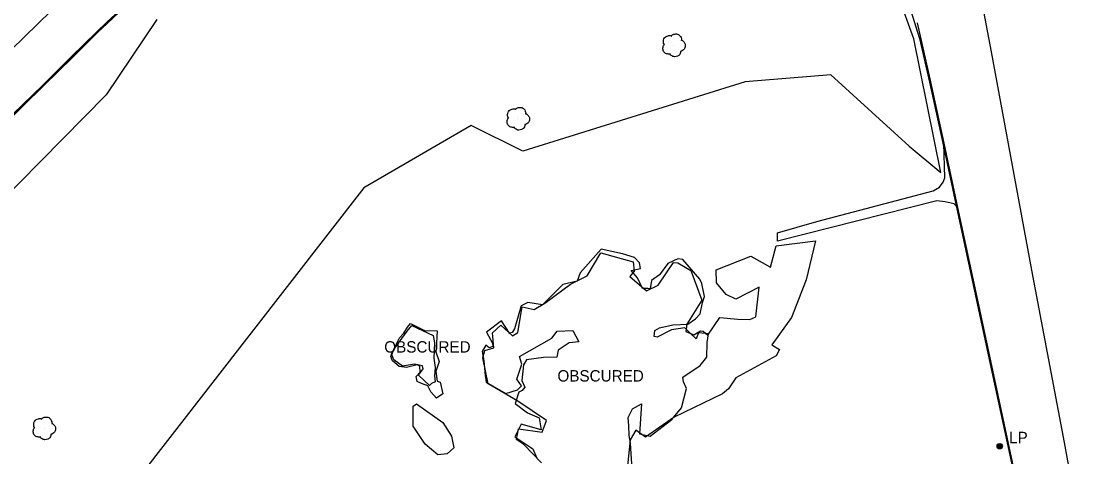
# Model space of a CAD drawing. Extents: x 368532 to 392481, y 10654822 to 10676899.
# Drawn here: x 374954.4 to 375423.4, y 10671119.3 to 10671309.9 of the extents above; entities that cross this region are included whole.
import ezdxf

# ---------------------------------------------------------------- set-up
doc = ezdxf.new("R2010")
doc.units = 0
for name, color, linetype in [('p_drainage conc drain', 7, 'Continuous'), ('p_dtm obscured area', 7, 'Continuous'), ('p_road - paved curb', 7, 'Continuous'), ('p_road guard rails', 7, 'Continuous'), ('p_road paint stripe', 7, 'Continuous'), ('p_structure constr area', 7, 'Continuous'), ('p_utility general pole', 7, 'Continuous'), ('p_veg tree', 7, 'Continuous'), ('p_veg woods', 7, 'Continuous')]:
    doc.layers.add(name, color=color, linetype=linetype)

msp = doc.modelspace()

# ---------------------------------------------------------------- linework, layer by layer
at = {"layer": 'p_drainage conc drain'}
for p, q in [((375359.42, 10671241.33), (375359, 10671256.53)), ((375357.15, 10671237.35), (375358.81, 10671239.52)), ((375358.81, 10671239.52), (375359.42, 10671241.33)), ((375303.34, 10671222.27), (375354.37, 10671235.67)), ((375354.37, 10671235.67), (375357.15, 10671237.35)), ((375356.05, 10671231.36), (375286.15, 10671213.72)), ((375359.64, 10671230.95), (375356.05, 10671231.36)), ((375363.54, 10671230.07), (375359.64, 10671230.95)), ((375365.09, 10671228.36), (375363.54, 10671230.07)), ((375286.11, 10671217.37), (375303.34, 10671222.27)), ((375286.15, 10671213.72), (375286.11, 10671217.37))]:
    msp.add_line(p, q, dxfattribs=at)
at = {"layer": 'p_dtm obscured area'}
msp.add_lwpolyline([(375222.15, 10671116.12), (375221.65, 10671125.04), (375221.02, 10671128.72), (375220.81, 10671132.71), (375220.55, 10671136.33), (375222.51, 10671140.19), (375226.42, 10671142.38), (375225.57, 10671129.2), (375230.25, 10671128.21), (375239.8, 10671135.51), (375243.95, 10671140.64), (375246.15, 10671149.12), (375244.87, 10671151.98), (375244.55, 10671154.02), (375252.13, 10671159.13), (375255.1, 10671162.77), (375255.31, 10671169.27), (375255.8, 10671173.05), (375251.48, 10671173.53), (375250.44, 10671170.92), (375247.99, 10671173.23), (375245.49, 10671175.63), (375239.65, 10671174.85), (375233.32, 10671171.56), (375231.94, 10671171.89), (375232.35, 10671174.5), (375234.37, 10671175.62), (375240.23, 10671177.02), (375246.79, 10671177.27), (375250.05, 10671179.58), (375252.12, 10671181.78), (375253.22, 10671186.78), (375254.11, 10671189.47), (375252.95, 10671195.09), (375252.02, 10671197.04), (375244.53, 10671205.58), (375242.35, 10671205.84), (375237.92, 10671203.88), (375234.39, 10671198.85), (375230.87, 10671196.39), (375230.27, 10671192.82), (375229.23, 10671192.91), (375226.93, 10671192.94), (375224.69, 10671197.52), (375221.88, 10671200.84), (375225.96, 10671201.64), (375225.56, 10671204.13), (375223.38, 10671206.5), (375218.14, 10671208.17), (375208.74, 10671210.15), (375199.59, 10671199.82), (375198.2, 10671196.1), (375191.97, 10671194.7), (375183.01, 10671185.78), (375176.53, 10671186.8), (375173.6, 10671185.33), (375170.78, 10671175.18), (375169.7, 10671173.61), (375168.59, 10671173.38), (375165.02, 10671178.79), (375158.38, 10671173.76), (375161.13, 10671169), (375161.18, 10671167.47), (375159.6, 10671166.93), (375158.1, 10671168.15), (375156.5, 10671165.26), (375157.21, 10671161.18), (375157.9, 10671154.8), (375158.28, 10671151.91), (375161.08, 10671150.26), (375166.86, 10671146.97), (375171.99, 10671148.54), (375173.82, 10671150.28), (375171.73, 10671153.16), (375173.9, 10671159.83), (375172.86, 10671163.07), (375187.07, 10671171.09), (375189.46, 10671174.18), (375196.36, 10671174.55), (375198.96, 10671169.55), (375194.66, 10671169.18), (375189.86, 10671165.84), (375189.31, 10671162.87), (375183.52, 10671162.64), (375175.95, 10671161.72), (375174.69, 10671159.54), (375173.9, 10671152.58), (375175.27, 10671149.64), (375174.04, 10671148.27), (375172.58, 10671147.47), (375171.07, 10671142.52), (375176.42, 10671138.39), (375181.51, 10671136.3), (375182.37, 10671131.02), (375173.6, 10671133.51), (375170.93, 10671127.87), (375178.76, 10671122.74), (375180.52, 10671118.57)], dxfattribs=at)
msp.add_lwpolyline([(375116.94, 10671164.56), (375120.32, 10671171.29), (375122.12, 10671173.38), (375123.8, 10671175.91), (375125.18, 10671177.65), (375131.21, 10671174.48), (375136.76, 10671174.42), (375136.54, 10671169.13), (375136.25, 10671165.1), (375137.64, 10671160.98), (375136.23, 10671156.5), (375136.81, 10671152.36), (375138.16, 10671151.89), (375139.31, 10671146.81), (375136.56, 10671144.86), (375134.03, 10671147.57), (375132.76, 10671150.21), (375129.92, 10671151.31), (375128, 10671152.14), (375127.59, 10671154.36), (375129.4, 10671156.27), (375129.23, 10671158.82), (375128.05, 10671159.48), (375123.37, 10671158.32), (375120.18, 10671158.81), (375117.14, 10671161.16), (375116.43, 10671163.12)], close=True, dxfattribs=at)
at = {"layer": 'p_road - paved curb'}
for p, q in [((375369.19, 10671353.44), (375379.78, 10671296.54)), ((374991.8, 10671309.3), (374999.57, 10671316.56)), ((374992.04, 10671309.05), (374999.81, 10671316.31)), ((374976.25, 10671294.1), (374987.75, 10671305.41)), ((374976.49, 10671293.85), (374988, 10671305.16)), ((374987.75, 10671305.41), (374991.8, 10671309.3)), ((374988, 10671305.16), (374992.04, 10671309.05)), ((375347.31, 10671309.25), (375352.93, 10671284.76)), ((375379.78, 10671296.54), (375397.57, 10671200.96)), ((374970.59, 10671288.48), (374976.25, 10671294.1)), ((374970.83, 10671288.23), (374976.49, 10671293.85)), ((374963.87, 10671281.89), (374970.59, 10671288.48)), ((374964.12, 10671281.64), (374970.83, 10671288.23)), ((374955.16, 10671273.37), (374963.87, 10671281.89)), ((374955.41, 10671273.12), (374964.12, 10671281.64)), ((375352.93, 10671284.76), (375359, 10671256.53)), ((374950.68, 10671268.98), (374955.16, 10671273.37)), ((374950.92, 10671268.73), (374955.41, 10671273.12)), ((375359, 10671256.53), (375365.09, 10671228.36)), ((375365.09, 10671228.36), (375375.19, 10671181.66)), ((375397.57, 10671200.96), (375411.85, 10671125.48)), ((375375.19, 10671181.66), (375394.3, 10671092.6)), ((375411.85, 10671125.48), (375423.43, 10671062.95))]:
    msp.add_line(p, q, dxfattribs=at)
msp.add_lwpolyline([(374950.57, 10671269.09), (374955.06, 10671273.48), (374963.77, 10671282), (374970.48, 10671288.59), (374976.14, 10671294.21), (374987.65, 10671305.52), (374991.7, 10671309.41), (374999.47, 10671316.67), (375005.13, 10671322.02), (375022.3, 10671337.98), (375035.04, 10671349.69), (375044.62, 10671358.5), (375048.92, 10671362.41), (375058.89, 10671371.61), (375069.94, 10671381.67), (375078.09, 10671389.26)], dxfattribs=at)
at = {"layer": 'p_road guard rails'}
for p, q in [((375343.08, 10671319.28), (375348.4, 10671302.45)), ((375348.4, 10671302.45), (375352.72, 10671283.37)), ((375352.72, 10671283.37), (375358.55, 10671256.54)), ((375358.55, 10671256.54), (375364.74, 10671227.84)), ((375364.74, 10671227.84), (375380.04, 10671156.42)), ((375380.04, 10671156.42), (375389.67, 10671112.43))]:
    msp.add_line(p, q, dxfattribs=at)
at = {"layer": 'p_road paint stripe'}
msp.add_line((374931.39, 10671279.41), (374990.42, 10671337.04), dxfattribs=at)
at = {"layer": 'p_structure constr area'}
for p, q in [((375345.92, 10671302.27), (375331.08, 10671343.3)), ((375013.86, 10671310.7), (374991.57, 10671277.83)), ((375357.8, 10671243.68), (375345.92, 10671302.27)), ((375309.5, 10671286.5), (375271.88, 10671283.45)), ((375343.87, 10671255.23), (375309.5, 10671286.5)), ((375271.88, 10671283.45), (375174.35, 10671253.01)), ((374991.57, 10671277.83), (374940.24, 10671225.7)), ((375151.7, 10671264.36), (375104.7, 10671237)), ((375174.35, 10671253.01), (375151.7, 10671264.36)), ((375343.87, 10671255.23), (375357.8, 10671243.68)), ((375104.7, 10671237), (374989.59, 10671089.24))]:
    msp.add_line(p, q, dxfattribs=at)
at = {"layer": 'p_utility general pole'}
for radius in [1.19, 0.901, 0.608, 0.337, 0.12]:
    msp.add_circle((375383.56, 10671123.82), radius, dxfattribs=at)
at = {"layer": 'p_veg tree'}
for p, q in [((375240.56, 10671299.52), (375240.56, 10671299.52)), ((375172.22, 10671267.39), (375172.22, 10671267.39)), ((374964.35, 10671131.72), (374964.35, 10671131.72))]:
    msp.add_line(p, q, dxfattribs=at)
for points in [[(375238.95, 10671295.68), (375237.4, 10671295.75), (375236.15, 10671296.78), (375235.83, 10671298.25), (375235.98, 10671299.09), (375236.35, 10671299.69), (375236.46, 10671299.79), (375236.4, 10671299.89), (375236.06, 10671300.78), (375236.48, 10671302.67), (375238.1, 10671303.68), (375239.4, 10671303.54), (375239.54, 10671303.49), (375239.61, 10671303.58), (375240.61, 10671304.28), (375242.23, 10671304.34), (375243.55, 10671303.32), (375243.93, 10671302.3), (375243.97, 10671301.75), (375243.95, 10671301.64), (375244.05, 10671301.64), (375244.64, 10671301.31), (375245.44, 10671300.31), (375245.6, 10671298.75), (375244.92, 10671297.53), (375243.94, 10671296.95), (375243.69, 10671296.9), (375243.63, 10671296.85), (375243.62, 10671296.79), (375243.55, 10671296.34), (375243.18, 10671295.44), (375242.21, 10671294.71), (375240.98, 10671294.43), (375239.5, 10671295.04), (375238.93, 10671295.69)], [(375170.61, 10671263.55), (375169.05, 10671263.62), (375167.81, 10671264.64), (375167.49, 10671266.11), (375167.63, 10671266.95), (375168, 10671267.55), (375168.11, 10671267.65), (375168.05, 10671267.75), (375167.71, 10671268.65), (375168.13, 10671270.53), (375169.76, 10671271.54), (375171.05, 10671271.41), (375171.19, 10671271.35), (375171.27, 10671271.45), (375172.27, 10671272.14), (375173.88, 10671272.2), (375175.2, 10671271.18), (375175.58, 10671270.16), (375175.62, 10671269.61), (375175.6, 10671269.5), (375175.71, 10671269.5), (375176.29, 10671269.17), (375177.09, 10671268.17), (375177.26, 10671266.61), (375176.58, 10671265.4), (375175.6, 10671264.81), (375175.34, 10671264.76), (375175.29, 10671264.72), (375175.27, 10671264.65), (375175.2, 10671264.2), (375174.83, 10671263.3), (375173.86, 10671262.57), (375172.63, 10671262.3), (375171.15, 10671262.91), (375170.59, 10671263.56)], [(374962.74, 10671127.88), (374961.19, 10671127.95), (374959.94, 10671128.97), (374959.62, 10671130.44), (374959.77, 10671131.28), (374960.14, 10671131.88), (374960.24, 10671131.99), (374960.19, 10671132.08), (374959.85, 10671132.98), (374960.27, 10671134.86), (374961.89, 10671135.87), (374963.19, 10671135.74), (374963.32, 10671135.68), (374963.4, 10671135.78), (374964.4, 10671136.47), (374966.02, 10671136.53), (374967.34, 10671135.51), (374967.72, 10671134.49), (374967.76, 10671133.94), (374967.74, 10671133.83), (374967.84, 10671133.83), (374968.43, 10671133.5), (374969.23, 10671132.5), (374969.39, 10671130.94), (374968.71, 10671129.73), (374967.73, 10671129.14), (374967.47, 10671129.09), (374967.42, 10671129.05), (374967.41, 10671128.98), (374967.33, 10671128.54), (374966.97, 10671127.63), (374966, 10671126.9), (374964.77, 10671126.63), (374963.29, 10671127.24), (374962.72, 10671127.89)]]:
    msp.add_spline(points, degree=3, dxfattribs=at)
at = {"layer": 'p_veg woods'}
msp.add_lwpolyline([(375182.6, 10671116.48), (375174.89, 10671124.5), (375171.65, 10671126.83), (375172.51, 10671131.36), (375182.85, 10671129.92), (375184.77, 10671135.13), (375172.24, 10671143.51), (375159.16, 10671151.18), (375156.82, 10671162.47), (375157.69, 10671165.78), (375161.64, 10671166.96), (375161.1, 10671173.42), (375164.78, 10671176.82), (375169.8, 10671172.15), (375172.26, 10671173.68), (375174.13, 10671184.85), (375179.39, 10671183.69), (375184.05, 10671186.52), (375195.34, 10671194.79), (375202.54, 10671198.48), (375208.63, 10671208.59), (375222.77, 10671204.61), (375223.21, 10671200.5), (375221.34, 10671198.12), (375228.6, 10671191.96), (375233.79, 10671194.33), (375240.46, 10671204.27), (375242.44, 10671204.09), (375248.1, 10671200.86), (375252.86, 10671187.74), (375246.25, 10671177.34), (375245.91, 10671174.1), (375249.34, 10671172.6), (375252.36, 10671174.32), (375253.54, 10671174.22), (375255.56, 10671172.47), (375260.78, 10671180.27), (375268.66, 10671179.52), (375273.99, 10671179.29), (375276.62, 10671180.48), (375278.08, 10671193.47), (375267.74, 10671188.31), (375263.64, 10671190.26), (375259.27, 10671195.45), (375259.12, 10671201.04), (375274.43, 10671207.1), (375283.05, 10671202.29), (375285.53, 10671211.61), (375302.72, 10671213.77), (375298.59, 10671196.69), (375292.27, 10671180.25), (375283.56, 10671168.27), (375287.03, 10671166.2), (375285.44, 10671163.44), (375267.75, 10671153.78), (375264.64, 10671148.89), (375261.97, 10671146.73), (375240.72, 10671136.5), (375228.21, 10671127.75), (375224.02, 10671130.84), (375221.5, 10671126.62), (375220.32, 10671115.26)], dxfattribs=at)
for points in [[(375128.55, 10671154.91), (375130.6, 10671157.66), (375130.32, 10671159.04), (375126.88, 10671159.75), (375121.59, 10671158.87), (375117.86, 10671161.64), (375116.91, 10671163.93), (375117.74, 10671166.2), (375123.59, 10671174.26), (375125.66, 10671176.73), (375135.01, 10671172.3), (375135.7, 10671169.17), (375135.4, 10671162.43), (375135.98, 10671158.34), (375135.7, 10671154.71), (375135.9, 10671152.01), (375134.31, 10671151.25), (375133.37, 10671150.47), (375133.37, 10671150.47)], [(375131.47, 10671124.67), (375126.29, 10671132.62), (375126.3, 10671141.4), (375127.77, 10671142.4), (375139.24, 10671134.26), (375143.03, 10671128.25), (375144.11, 10671123.11), (375141.19, 10671120.51), (375137.12, 10671120.04)]]:
    msp.add_lwpolyline(points, close=True, dxfattribs=at)

# ---------------------------------------------------------------- texts
at = {"layer": 'p_dtm obscured area'}
for p in [(375111.73, 10671164.83), (375187.7, 10671152.15)]:
    msp.add_text(' OBSCURED', height=5, dxfattribs=at).set_placement(p)
at = {"layer": 'p_utility general pole'}
msp.add_text('LP', height=5, dxfattribs=at).set_placement((375387.68, 10671125.12))

doc.saveas('drawing.dxf')
